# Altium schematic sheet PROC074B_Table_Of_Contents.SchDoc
size 431 x 279 mm; Date: Not shown in title block; ApprovedBy: Not shown in title block; CheckedBy: Not shown in title block; Author: Not shown in title block; CompanyName: Not shown in title block; Engineer: Not shown in title block; Organization: Not shown in title block; Address1: Not shown in title block; Address2: Not shown in title block; Address3: Not shown in title block; Address4: Not shown in title block; DocumentNumber: 1; Revision: Use project parameter SCH_Rev; SheetNumber: 2; SheetTotal: 22; PageSetup: Record=PageOptions¦CenterHorizontal=True¦CenterVertical=True¦PrintScale=1.00¦XCorrection=1.00¦YCorrection=1.00¦PrintKind=0¦BorderSize=5000000¦LeftOffset=0¦BottomOffset=0¦Orientation=2¦PaperLength=1000¦PaperWidth=1000¦Scale=100¦PaperSource=15¦PrintQuality=600¦MediaType=1¦DitherType=10¦PaperKind=Letter¦PrintScaleMode=1
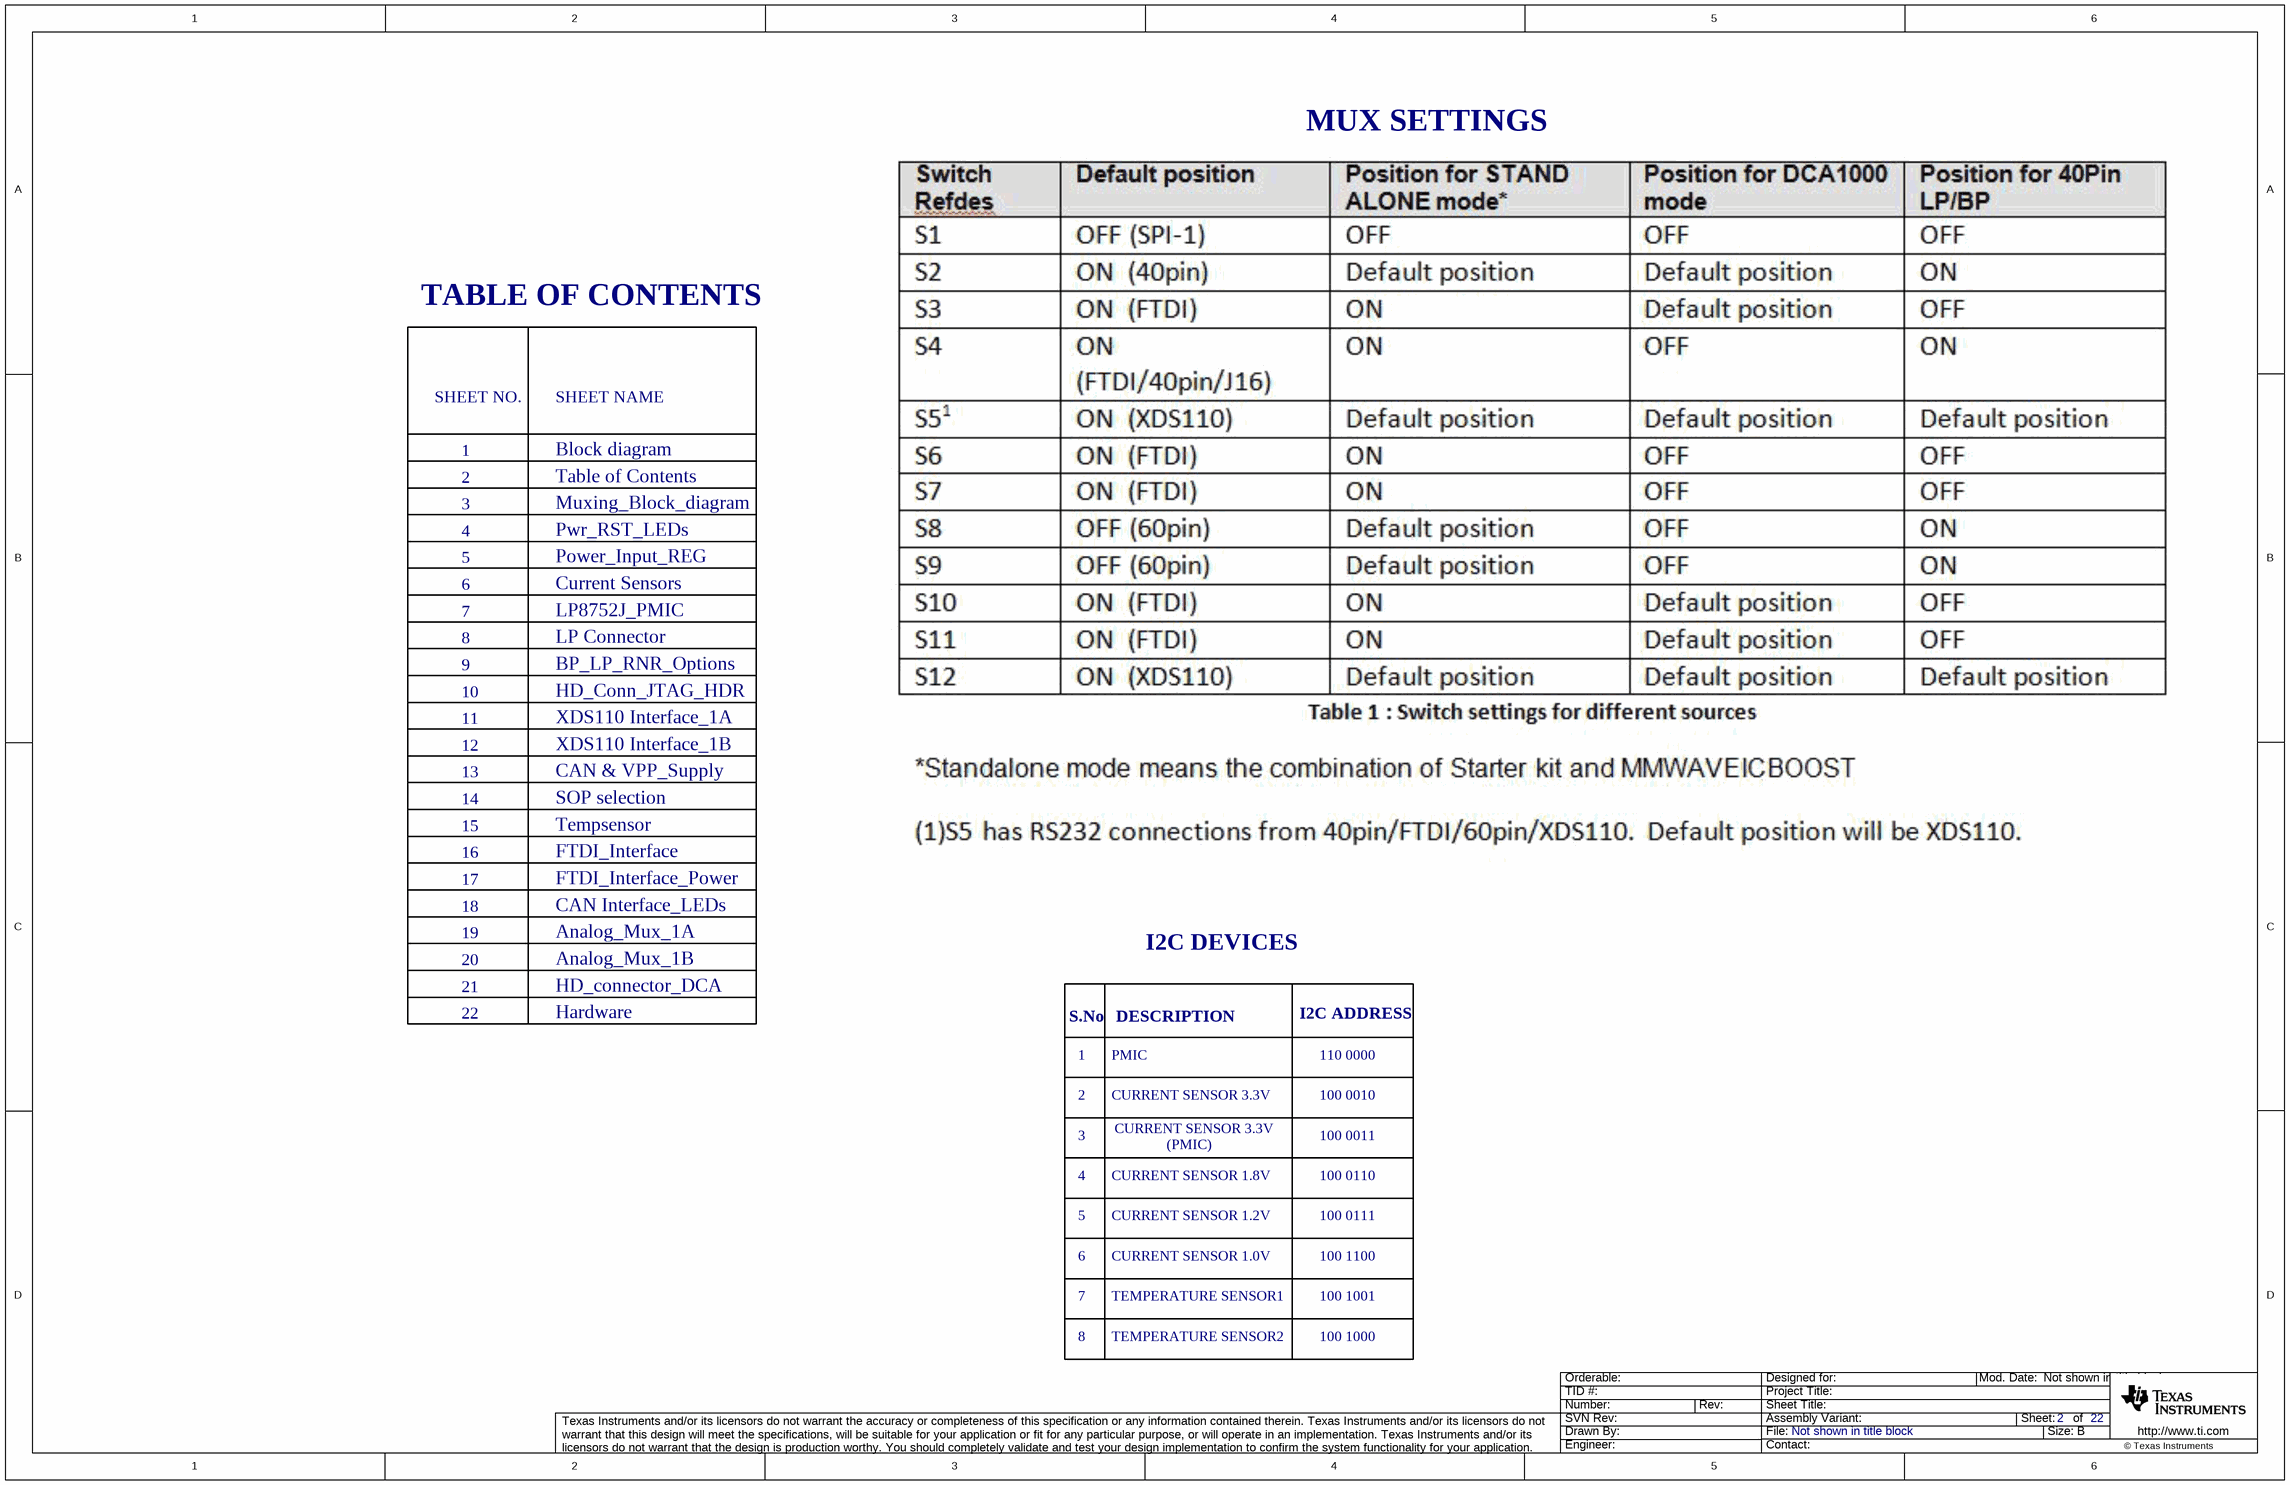
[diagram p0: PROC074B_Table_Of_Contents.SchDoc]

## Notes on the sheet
- MUX SETTINGS
- TABLE OF CONTENTS
- SHEET NO.
- SHEET NAME
- 1
- 2
- Table of Contents
- Block diagram
- 3
- 4
- 5
- Pwr_RST_LEDs
- Power_Input_REG
- Muxing_Block_diagram
- 7
- 6
- Current Sensors
- LP8752J_PMIC
- 8
- 9
- 10
- HD_Conn_JTAG_HDR
- LP Connector
- BP_LP_RNR_Options
- 11
- 12
- XDS110 Interface_1A
- XDS110 Interface_1B
- 13
- 14
- 15
- CAN & VPP_Supply
- SOP selection
- Tempsensor
- 16
- 17
- FTDI_Interface_Power
- FTDI_Interface
- 18
- 19
- 20
- Analog_Mux_1A
- CAN Interface_LEDs
- Analog_Mux_1B
- I2C DEVICES
- 21
- 22
- HD_connector_DCA
- Hardware
- S.No
- DESCRIPTION
- I2C ADDRESS
- PMIC
- CURRENT SENSOR 3.3V
- 100 0010
- 110 0000
- (PMIC)
- 100 0011
- CURRENT SENSOR 1.8V
- CURRENT SENSOR 1.2V
- 100 0110
- 100 0111
- CURRENT SENSOR 1.0V
- TEMPERATURE SENSOR1
- 100 1100
- 100 1001
- TEMPERATURE SENSOR2
- 100 1000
